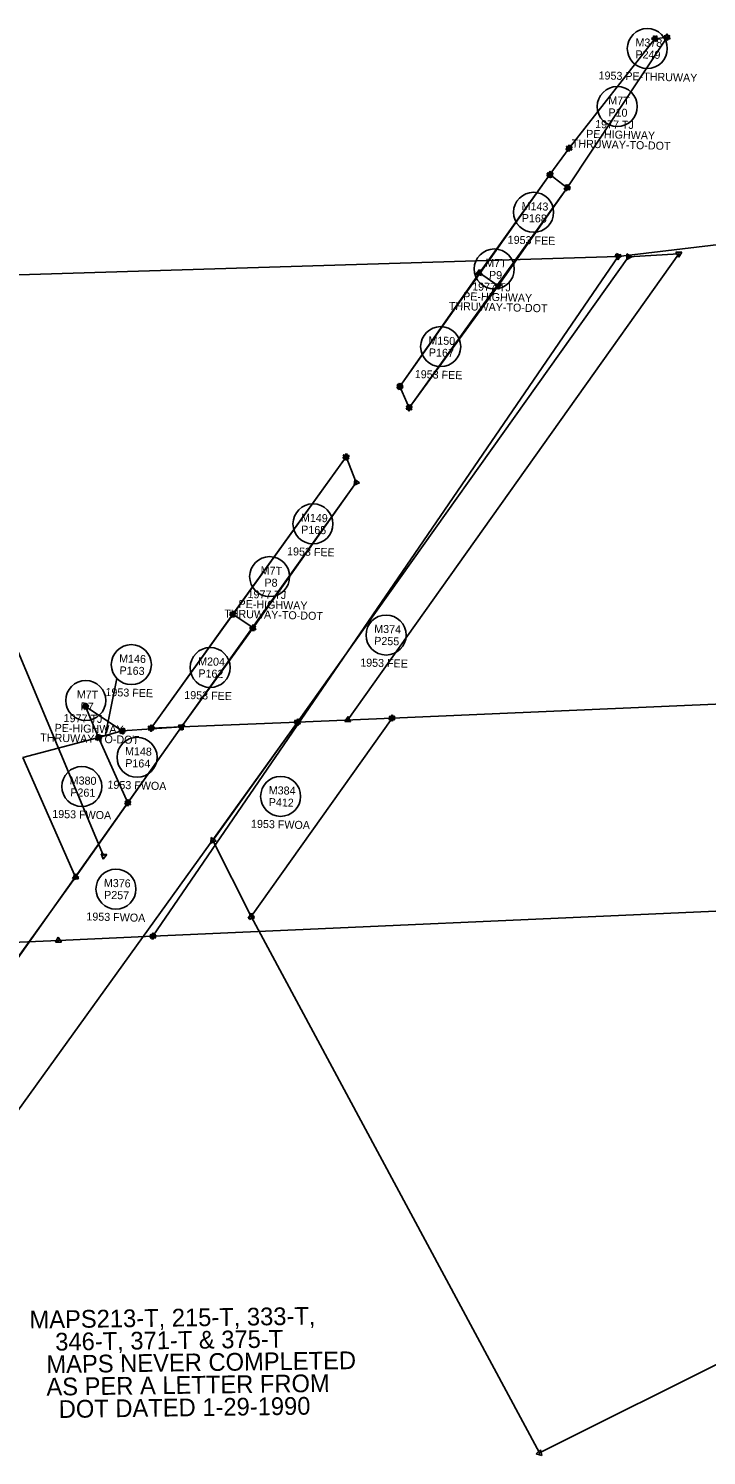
# Model space of a CAD drawing. Extents: x 325018 to 414989, y 1517547 to 1550415.
# Drawn here: x 360104 to 360548, y 1524421 to 1525357 of the extents above; entities that cross this region are included whole.
import ezdxf

# ---------------------------------------------------------------- set-up
doc = ezdxf.new("R2010")
doc.units = 0
for name, color, linetype in [('LAM_I', 7, 'Continuous'), ('Level 56', 7, 'Continuous'), ('MEE', 7, 'Continuous'), ('MHB', 7, 'Continuous'), ('MHBWOA', 7, 'Continuous'), ('MRBL1', 7, 'Continuous'), ('MRBL2', 7, 'Continuous'), ('MRBL3', 7, 'Continuous'), ('S_C', 7, 'Continuous')]:
    doc.layers.add(name, color=color, linetype=linetype)

msp = doc.modelspace()

# ---------------------------------------------------------------- linework, layer by layer
at = {"layer": 'Level 56'}
for centre in [(360509.52, 1525343.75), (360489.82, 1525305.7), (360434.97, 1525236.34), (360409.18, 1525199.15), (360374.05, 1525148.18), (360290.33, 1525031.94), (360261.93, 1524997.34), (360338.27, 1524958.99), (360171.24, 1524939.58), (360222.92, 1524937.68), (360141.36, 1524916.05), (360175, 1524878.79), (360138.8, 1524859.63), (360269.12, 1524853.16), (360161.16, 1524792.34)]:
    msp.add_circle(centre, 13.12, dxfattribs=at)
at = {"layer": 'MEE'}
for p, q in [((360522.5, 1525351.14), (360457, 1525252.39)), ((360514.56, 1525350.2), (360458.21, 1525278.44)), ((360514.56, 1525350.2), (360522.5, 1525351.14)), ((360458.21, 1525278.44), (360445.73, 1525261.05)), ((360347.21, 1525122.03), (360445.73, 1525261.05)), ((360457, 1525252.39), (360353.43, 1525108.09)), ((360353.43, 1525108.09), (360347.21, 1525122.03)), ((360184.24, 1524897.9), (360312, 1525075.85)), ((360312, 1525075.85), (360318.73, 1525059.13)), ((360318.73, 1525059.13), (360204.22, 1524898.78)), ((360141.3, 1524912.11), (360165.33, 1524896.16)), ((360149.8, 1524891.82), (360141.3, 1524912.11))]:
    msp.add_line(p, q, dxfattribs=at)
for points in [[(360512.37, 1525350.23), (360515.67, 1525352.08)], [(360513.44, 1525348.33), (360513.49, 1525352.1)], [(360513.49, 1525352.1), (360516.74, 1525350.17)], [(360515.67, 1525352.08), (360515.62, 1525348.3)], [(360520.58, 1525352.18), (360524.36, 1525352.28)], [(360522.56, 1525348.96), (360520.58, 1525352.18)], [(360520.65, 1525350), (360522.44, 1525353.32)], [(360522.44, 1525353.32), (360524.42, 1525350.1)], [(360524.36, 1525352.28), (360522.56, 1525348.96)], [(360515.62, 1525348.3), (360512.37, 1525350.23)], [(360516.74, 1525350.17), (360513.44, 1525348.33)], [(360524.42, 1525350.1), (360520.65, 1525350)], [(360456.2, 1525277.59), (360458.47, 1525280.61)], [(360459.95, 1525277.13), (360456.2, 1525277.59)], [(360457.95, 1525276.27), (360456.46, 1525279.75)], [(360456.46, 1525279.75), (360460.22, 1525279.29)], [(360460.22, 1525279.29), (360457.95, 1525276.27)], [(360458.47, 1525280.61), (360459.95, 1525277.13)], [(360443.57, 1525261.33), (360447.06, 1525262.78)], [(360446.57, 1525259.03), (360443.57, 1525261.33)], [(360443.74, 1525260.15), (360445.95, 1525263.22)], [(360447.5, 1525259.78), (360443.74, 1525260.15)], [(360445.53, 1525258.88), (360443.96, 1525262.31)], [(360443.96, 1525262.31), (360447.72, 1525261.95)], [(360447.72, 1525261.95), (360445.53, 1525258.88)], [(360445.95, 1525263.22), (360447.5, 1525259.78)], [(360447.06, 1525262.78), (360446.57, 1525259.03)], [(360455.03, 1525251.46), (360457.18, 1525254.57)], [(360458.8, 1525251.15), (360455.03, 1525251.46)], [(360455.32, 1525251), (360456.65, 1525254.54)], [(360459.05, 1525251.62), (360455.32, 1525251)], [(360456.65, 1525254.54), (360459.05, 1525251.62)], [(360457.18, 1525254.57), (360458.8, 1525251.15)], [(360345.23, 1525121.14), (360347.44, 1525124.2)], [(360348.98, 1525120.75), (360345.23, 1525121.14)], [(360347.01, 1525119.86), (360345.44, 1525123.29)], [(360345.44, 1525123.29), (360349.2, 1525122.94)], [(360349.2, 1525122.94), (360347.01, 1525119.86)], [(360347.44, 1525124.2), (360348.98, 1525120.75)], [(360353.21, 1525105.92), (360351.66, 1525109.37)], [(360351.66, 1525109.37), (360355.42, 1525108.99)], [(360355.42, 1525108.99), (360353.21, 1525105.92)], [(360309.99, 1525074.99), (360312.26, 1525078.01)], [(360313.74, 1525074.54), (360309.99, 1525074.99)], [(360312.26, 1525078.01), (360313.74, 1525074.54)], [(360317.42, 1525057.38), (360317.87, 1525061.13)], [(360320.89, 1525058.87), (360317.42, 1525057.38)], [(360317.87, 1525061.13), (360320.89, 1525058.87)], [(360139.12, 1524912.25), (360142.5, 1524913.93)], [(360142.27, 1524910.16), (360139.12, 1524912.25)], [(360139.29, 1524911.27), (360141.57, 1524914.28)], [(360141.57, 1524914.28), (360143.03, 1524910.79)], [(360142.5, 1524913.93), (360142.27, 1524910.16)], [(360143.03, 1524910.79), (360139.29, 1524911.27)], [(360148.85, 1524889.86), (360148.58, 1524893.63)], [(360148.58, 1524893.63), (360151.98, 1524891.98)], [(360163.95, 1524894.47), (360164.54, 1524898.2)], [(360167.48, 1524895.82), (360163.95, 1524894.47)], [(360164.54, 1524898.2), (360167.48, 1524895.82)], [(360182.31, 1524898.91), (360186.08, 1524899.08)], [(360184.34, 1524895.73), (360182.31, 1524898.91)], [(360184.03, 1524895.73), (360182.47, 1524899.17)], [(360182.47, 1524899.17), (360186.23, 1524898.8)], [(360186.23, 1524898.8), (360184.03, 1524895.73)], [(360186.08, 1524899.08), (360184.34, 1524895.73)], [(360202.04, 1524898.84), (360205.36, 1524900.64)], [(360205.26, 1524896.86), (360202.04, 1524898.84)], [(360205.36, 1524900.64), (360205.26, 1524896.86)], [(360151.98, 1524891.98), (360148.85, 1524889.86)]]:
    msp.add_lwpolyline(points, dxfattribs=at)
for centre, radius in [((360514.56, 1525350.2), 0.227), ((360514.56, 1525350.2), 0.227), ((360522.5, 1525351.14), 0.227), ((360522.5, 1525351.14), 0.227), ((360458.21, 1525278.44), 0.227), ((360458.21, 1525278.44), 0.227), ((360445.73, 1525261.05), 1.09), ((360445.73, 1525261.05), 1.09), ((360445.73, 1525261.05), 0.227), ((360457, 1525252.39), 0.227), ((360457, 1525252.39), 0.227), ((360347.22, 1525122.03), 1.09), ((360347.21, 1525122.03), 1.09), ((360353.43, 1525108.09), 0.227), ((360312, 1525075.85), 0.227), ((360318.73, 1525059.13), 0.227), ((360141.3, 1524912.11), 1.09), ((360141.3, 1524912.11), 1.09), ((360165.33, 1524896.16), 0.227), ((360184.24, 1524897.9), 1.09), ((360184.24, 1524897.91), 1.09), ((360204.22, 1524898.78), 0.227), ((360149.8, 1524891.82), 0.227)]:
    msp.add_circle(centre, radius, dxfattribs=at)
at = {"layer": 'MHB'}
for p, q in [((360399.41, 1525196.58), (360445.73, 1525261.05)), ((360445.73, 1525261.05), (360457, 1525252.39)), ((360457, 1525252.39), (360411.79, 1525188.11)), ((360280.21, 1524901.81), (360497.18, 1525207.19)), ((360530.19, 1525209.06), (360313.18, 1524903.29)), ((360497.18, 1525207.19), (360530.19, 1525209.06)), ((360399.41, 1525196.58), (360347.21, 1525122.03)), ((360411.79, 1525188.11), (360399.41, 1525196.58)), ((360353.43, 1525108.09), (360411.79, 1525188.11)), ((360237.83, 1524972.71), (360312, 1525075.85)), ((360318.73, 1525059.13), (360251.03, 1524963.68)), ((360184.24, 1524897.9), (360237.83, 1524972.71)), ((360251.03, 1524963.68), (360237.83, 1524972.71)), ((360251.03, 1524963.68), (360204.22, 1524898.78)), ((360204.22, 1524898.78), (360184.24, 1524897.9))]:
    msp.add_line(p, q, dxfattribs=at)
for points in [[(360443.57, 1525261.33), (360447.06, 1525262.78)], [(360446.57, 1525259.03), (360443.57, 1525261.33)], [(360445.52, 1525258.88), (360443.96, 1525262.32)], [(360443.96, 1525262.32), (360447.72, 1525261.95)], [(360447.72, 1525261.95), (360445.52, 1525258.88)], [(360447.06, 1525262.78), (360446.57, 1525259.03)], [(360455.64, 1525254.09), (360459.16, 1525252.72)], [(360456.21, 1525250.36), (360455.64, 1525254.09)], [(360459.16, 1525252.72), (360456.21, 1525250.36)], [(360496.06, 1525205.31), (360496.13, 1525209.09)], [(360499.36, 1525207.14), (360496.06, 1525205.31)], [(360496.13, 1525209.09), (360499.36, 1525207.14)], [(360528.32, 1525210.19), (360532.09, 1525210.12)], [(360530.14, 1525206.88), (360528.32, 1525210.19)], [(360532.09, 1525210.12), (360530.14, 1525206.88)], [(360397.27, 1525196.2), (360400.16, 1525198.63)], [(360400.81, 1525194.91), (360397.27, 1525196.2)], [(360397.43, 1525195.66), (360399.6, 1525198.76)], [(360401.19, 1525195.33), (360397.43, 1525195.66)], [(360399.6, 1525198.76), (360401.19, 1525195.33)], [(360400.16, 1525198.63), (360400.81, 1525194.91)], [(360409.74, 1525188.85), (360413.46, 1525189.53)], [(360412.18, 1525185.97), (360409.74, 1525188.85)], [(360411.56, 1525185.94), (360410.03, 1525189.4)], [(360410.03, 1525189.4), (360413.79, 1525188.99)], [(360413.79, 1525188.99), (360411.56, 1525185.94)], [(360413.46, 1525189.53), (360412.18, 1525185.97)], [(360345.94, 1525120.25), (360346.31, 1525124.02)], [(360349.38, 1525121.82), (360345.94, 1525120.25)], [(360346.31, 1525124.02), (360349.38, 1525121.82)], [(360351.43, 1525107.2), (360353.66, 1525110.25)], [(360353.66, 1525110.25), (360355.19, 1525106.8)], [(360355.19, 1525106.8), (360351.43, 1525107.2)], [(360311.78, 1525073.68), (360310.23, 1525077.12)], [(360310.23, 1525077.12), (360313.99, 1525076.75)], [(360310.28, 1525077.19), (360314.02, 1525076.66)], [(360311.69, 1525073.69), (360310.28, 1525077.19)], [(360314.02, 1525076.66), (360311.69, 1525073.69)], [(360313.99, 1525076.75), (360311.78, 1525073.68)], [(360317.43, 1525057.38), (360317.87, 1525061.13)], [(360320.9, 1525058.87), (360317.43, 1525057.38)], [(360317.87, 1525061.13), (360320.9, 1525058.87)], [(360235.68, 1524972.34), (360238.58, 1524974.76)], [(360239.23, 1524971.04), (360235.68, 1524972.34)], [(360237.62, 1524970.54), (360236.06, 1524973.98)], [(360236.06, 1524973.98), (360239.82, 1524973.61)], [(360239.82, 1524973.61), (360237.62, 1524970.54)], [(360238.58, 1524974.76), (360239.23, 1524971.04)], [(360248.98, 1524964.43), (360252.7, 1524965.09)], [(360251.42, 1524961.54), (360248.98, 1524964.43)], [(360249.04, 1524962.79), (360251.25, 1524965.85)], [(360252.8, 1524962.41), (360249.04, 1524962.79)], [(360251.25, 1524965.85), (360252.8, 1524962.41)], [(360252.7, 1524965.09), (360251.42, 1524961.54)], [(360140.54, 1524910.06), (360139.91, 1524913.79)], [(360139.91, 1524913.79), (360143.45, 1524912.47)], [(360143.45, 1524912.47), (360140.54, 1524910.06)], [(360280.01, 1524899.63), (360278.44, 1524903.07)], [(360278.44, 1524903.07), (360282.2, 1524902.72)], [(360282.2, 1524902.72), (360280.01, 1524899.63)], [(360311.19, 1524902.38), (360313.38, 1524905.46)], [(360314.95, 1524902.02), (360311.19, 1524902.38)], [(360313.38, 1524905.46), (360314.95, 1524902.02)], [(360148.85, 1524889.86), (360148.58, 1524893.63)], [(360148.58, 1524893.63), (360151.98, 1524891.98)], [(360163.15, 1524896.3), (360166.53, 1524897.98)], [(360166.3, 1524894.21), (360163.15, 1524896.3)], [(360163.22, 1524896.71), (360166.85, 1524897.72)], [(360165.92, 1524894.06), (360163.22, 1524896.71)], [(360166.85, 1524897.72), (360165.92, 1524894.06)], [(360166.53, 1524897.98), (360166.3, 1524894.21)], [(360182.33, 1524896.87), (360184.3, 1524900.09)], [(360186.1, 1524896.76), (360182.33, 1524896.87)], [(360184.3, 1524900.09), (360186.1, 1524896.76)], [(360202.04, 1524898.84), (360205.36, 1524900.64)], [(360205.26, 1524896.86), (360202.04, 1524898.84)], [(360205.36, 1524900.64), (360205.26, 1524896.86)], [(360151.98, 1524891.98), (360148.85, 1524889.86)]]:
    msp.add_lwpolyline(points, dxfattribs=at)
for centre, radius in [((360445.73, 1525261.05), 1.09), ((360445.73, 1525261.05), 1.09), ((360457, 1525252.39), 0.227), ((360497.18, 1525207.19), 0.227), ((360530.19, 1525209.06), 0.227), ((360399.41, 1525196.58), 1.09), ((360399.41, 1525196.58), 0.227), ((360411.79, 1525188.11), 1.09), ((360411.79, 1525188.11), 0.227), ((360347.21, 1525122.03), 0.227), ((360353.43, 1525108.09), 0.227), ((360312, 1525075.85), 1.09), ((360312, 1525075.85), 1.09), ((360318.73, 1525059.13), 0.227), ((360237.83, 1524972.72), 1.09), ((360237.83, 1524972.71), 0.227), ((360251.03, 1524963.68), 1.09), ((360251.03, 1524963.68), 0.227), ((360141.3, 1524912.11), 0.227), ((360280.21, 1524901.81), 1.09), ((360313.18, 1524903.28), 1.09), ((360165.33, 1524896.16), 1.09), ((360165.33, 1524896.16), 1.09), ((360184.24, 1524897.9), 0.227), ((360204.22, 1524898.78), 0.227), ((360149.8, 1524891.82), 0.227)]:
    msp.add_circle(centre, radius, dxfattribs=at)
at = {"layer": 'MHBWOA'}
for p, q in [((360926.64, 1524929.92), (360342.15, 1524904.58)), ((360342.15, 1524904.58), (360249.89, 1524774.32)), ((360342.15, 1524904.58), (360280.21, 1524901.81)), ((360204.22, 1524898.78), (360044.21, 1524673.02)), ((360092.69, 1524641.16), (360280.21, 1524901.81)), ((360165.33, 1524896.16), (360149.8, 1524891.82)), ((360204.22, 1524898.78), (360165.33, 1524896.16)), ((360168.89, 1524848.86), (360204.22, 1524898.78)), ((360280.21, 1524901.81), (360204.22, 1524898.78)), ((360280.21, 1524901.81), (360224.63, 1524824.24)), ((360149.8, 1524891.82), (360100.06, 1524878.72)), ((360149.8, 1524891.82), (360168.89, 1524848.86)), ((360100.06, 1524878.72), (360134.61, 1524800.19)), ((360134.61, 1524800.19), (360168.89, 1524848.86)), ((360224.63, 1524824.24), (360249.89, 1524774.32)), ((360134.61, 1524800.19), (360089.39, 1524737.1)), ((360249.89, 1524774.32), (360438.82, 1524422.43)), ((360438.82, 1524422.43), (361118.26, 1524762.34))]:
    msp.add_line(p, q, dxfattribs=at)
for points in [[(360278.22, 1524900.91), (360280.42, 1524903.98)], [(360278.27, 1524902.82), (360282.05, 1524902.99)], [(360280.31, 1524899.63), (360278.27, 1524902.82)], [(360278.28, 1524902.83), (360282.06, 1524902.98)], [(360280.3, 1524899.63), (360278.28, 1524902.83)], [(360280, 1524899.64), (360278.44, 1524903.08)], [(360278.44, 1524903.08), (360282.2, 1524902.7)], [(360282.2, 1524902.7), (360280, 1524899.64)], [(360282.06, 1524902.98), (360280.3, 1524899.63)], [(360282.05, 1524902.99), (360280.31, 1524899.63)], [(360280.42, 1524903.98), (360281.98, 1524900.54)], [(360340.16, 1524903.67), (360342.35, 1524906.76)], [(360343.93, 1524903.32), (360340.16, 1524903.67)], [(360340.21, 1524905.59), (360343.99, 1524905.76)], [(360342.24, 1524902.41), (360340.21, 1524905.59)], [(360340.24, 1524903.54), (360342.2, 1524906.77)], [(360344.01, 1524903.45), (360340.24, 1524903.54)], [(360342.2, 1524906.77), (360344.01, 1524903.45)], [(360343.99, 1524905.76), (360342.24, 1524902.41)], [(360342.35, 1524906.76), (360343.93, 1524903.32)], [(360147.69, 1524892.4), (360151.35, 1524893.36)], [(360148.01, 1524890.58), (360149.62, 1524894)], [(360149.62, 1524894), (360151.77, 1524890.89)], [(360151.35, 1524893.36), (360150.35, 1524889.72)], [(360163.28, 1524896.92), (360167.01, 1524897.56)], [(360165.7, 1524894.02), (360163.28, 1524896.92)], [(360167.01, 1524897.56), (360165.7, 1524894.02)], [(360202.04, 1524898.84), (360205.36, 1524900.64)], [(360205.26, 1524896.86), (360202.04, 1524898.84)], [(360202.26, 1524899.74), (360206.03, 1524900)], [(360204.37, 1524896.6), (360202.26, 1524899.74)], [(360204.02, 1524896.6), (360202.44, 1524900.04)], [(360202.44, 1524900.04), (360206.21, 1524899.69)], [(360206.21, 1524899.69), (360204.02, 1524896.6)], [(360206.03, 1524900), (360204.37, 1524896.6)], [(360205.36, 1524900.64), (360205.26, 1524896.86)], [(360281.98, 1524900.54), (360278.22, 1524900.91)], [(360150.35, 1524889.72), (360147.69, 1524892.4)], [(360151.77, 1524890.89), (360148.01, 1524890.58)], [(360166.9, 1524847.96), (360169.1, 1524851.03)], [(360170.66, 1524847.59), (360166.9, 1524847.96)], [(360168.7, 1524846.69), (360167.11, 1524850.12)], [(360167.11, 1524850.12), (360170.87, 1524849.78)], [(360170.87, 1524849.78), (360168.7, 1524846.69)], [(360169.1, 1524851.03), (360170.66, 1524847.59)], [(360223.39, 1524822.44), (360223.68, 1524826.21)], [(360226.8, 1524824.08), (360223.39, 1524822.44)], [(360223.68, 1524826.21), (360226.8, 1524824.08)], [(360132.62, 1524799.29), (360134.83, 1524802.36)], [(360133.33, 1524798.43), (360133.72, 1524802.18)], [(360136.78, 1524799.97), (360133.33, 1524798.43)], [(360133.72, 1524802.18), (360136.78, 1524799.97)], [(360134.83, 1524802.36), (360136.38, 1524798.91)], [(360136.38, 1524798.91), (360132.62, 1524799.29)], [(360247.92, 1524773.37), (360250.05, 1524776.5)], [(360251.69, 1524773.09), (360247.92, 1524773.37)], [(360248.68, 1524772.51), (360248.91, 1524776.28)], [(360252.06, 1524774.19), (360248.68, 1524772.51)], [(360248.91, 1524776.28), (360252.06, 1524774.19)], [(360250.05, 1524776.5), (360251.69, 1524773.09)], [(360436.69, 1524421.95), (360439.48, 1524424.5)], [(360440.29, 1524420.81), (360436.69, 1524421.95)], [(360439.48, 1524424.5), (360440.29, 1524420.81)]]:
    msp.add_lwpolyline(points, dxfattribs=at)
for centre, radius in [((360280.21, 1524901.81), 1.09), ((360280.21, 1524901.81), 1.09), ((360280.21, 1524901.81), 1.09), ((360280.21, 1524901.81), 1.09), ((360342.15, 1524904.58), 1.09), ((360342.15, 1524904.58), 1.09), ((360342.15, 1524904.58), 0.227), ((360165.33, 1524896.16), 0.227), ((360204.22, 1524898.78), 1.09), ((360204.22, 1524898.78), 1.09), ((360204.22, 1524898.78), 0.227), ((360149.8, 1524891.82), 1.09), ((360149.8, 1524891.82), 0.227), ((360168.89, 1524848.86), 1.09), ((360168.89, 1524848.86), 0.227), ((360224.63, 1524824.24), 0.227), ((360134.61, 1524800.19), 0.227), ((360134.61, 1524800.19), 0.227), ((360249.89, 1524774.32), 0.227), ((360249.89, 1524774.32), 0.227), ((360438.82, 1524422.43), 0.227)]:
    msp.add_circle(centre, radius, dxfattribs=at)
at = {"layer": 'MRBL1'}
for p, q in [((360490.4, 1525207.39), (360750.98, 1525238.11)), ((360185.4, 1524761.43), (360490.4, 1525207.39))]:
    msp.add_line(p, q, dxfattribs=at)
for points in [[(360489.35, 1525205.48), (360489.27, 1525209.26)], [(360489.27, 1525209.26), (360492.58, 1525207.44)], [(360492.58, 1525207.44), (360489.35, 1525205.48)], [(360185.23, 1524759.25), (360183.6, 1524762.65)], [(360183.6, 1524762.65), (360187.37, 1524762.37)], [(360187.37, 1524762.37), (360185.23, 1524759.25)]]:
    msp.add_lwpolyline(points, dxfattribs=at)
for centre, radius in [((360490.4, 1525207.39), 0.227), ((360185.4, 1524761.43), 1.09)]:
    msp.add_circle(centre, radius, dxfattribs=at)
at = {"layer": 'MRBL2'}
for p, q in [((360490.4, 1525207.39), (359994.63, 1525192.19)), ((360185.4, 1524761.43), (360836.78, 1524790.6)), ((357680.4, 1524649.21), (360123.46, 1524758.65)), ((360123.46, 1524758.65), (360185.4, 1524761.43))]:
    msp.add_line(p, q, dxfattribs=at)
for points in [[(360488.48, 1525208.43), (360492.25, 1525208.54)], [(360490.47, 1525205.22), (360488.48, 1525208.43)], [(360492.25, 1525208.54), (360490.47, 1525205.22)], [(360183.56, 1524760.25), (360185.3, 1524763.6)], [(360185.3, 1524763.6), (360187.33, 1524760.42)], [(360121.62, 1524757.47), (360123.36, 1524760.83)], [(360125.4, 1524757.64), (360121.62, 1524757.47)], [(360123.36, 1524760.83), (360125.4, 1524757.64)], [(360187.33, 1524760.42), (360183.56, 1524760.25)]]:
    msp.add_lwpolyline(points, dxfattribs=at)
for centre, radius in [((360490.4, 1525207.39), 1.09), ((360123.46, 1524758.65), 0.227), ((360185.4, 1524761.43), 0.227)]:
    msp.add_circle(centre, radius, dxfattribs=at)
at = {"layer": 'MRBL3'}
msp.add_line((359994.63, 1525192.19), (360153.1, 1524814.1), dxfattribs=at)
for points in [[(360151.36, 1524815.42), (360155.11, 1524814.94)], [(360152.82, 1524811.93), (360151.36, 1524815.42)], [(360155.11, 1524814.94), (360152.82, 1524811.93)]]:
    msp.add_lwpolyline(points, dxfattribs=at)
msp.add_circle((360153.1, 1524814.09), 1.09, dxfattribs=at)
at = {"layer": 'S_C'}
msp.add_line((360154.23, 1524893.69), (360161.73, 1524930.54), dxfattribs=at)

# ---------------------------------------------------------------- texts
at = {"layer": 'LAM_I'}
for s, p in [('MAPS213-T, 215-T, 333-T,', (360104.53, 1524504.11)), ('346-T, 371-T & 375-T', (360121.42, 1524489.59)), ('MAPS NEVER COMPLETED', (360115.63, 1524474.78)), ('AS PER A LETTER FROM', (360115.65, 1524460.04)), ('DOT DATED 1-29-1990', (360123.71, 1524445.4))]:
    msp.add_text(s, height=11.6264, rotation=0.76966, dxfattribs=at).set_placement(p)
at = {"layer": 'Level 56'}
for s, height, p in [('P249', 5.249, (360501.67, 1525337.39)), ('M378', 5.249, (360501.68, 1525345.26)), ('1953 PE-THRUWAY', 5.2493, (360477.53, 1525323.56)), ('M7T', 5.249, (360483.88, 1525307.17)), ('1977 TJ', 5.249, (360475.28, 1525291.63)), ('P10', 5.249, (360483.97, 1525299.29)), ('PE-HIGHWAY', 5.249, (360469.36, 1525285.21)), ('THRUWAY-TO-DOT', 5.2493, (360459.97, 1525278.88)), ('M143', 5.249, (360427.06, 1525237.86)), ('P168', 5.249, (360427.18, 1525229.98)), ('1953 FEE', 5.249, (360417.95, 1525215.76)), ('M7T', 5.249, (360403.23, 1525200.62)), ('P9', 5.249, (360405.68, 1525192.68)), ('PE-HIGHWAY', 5.249, (360388.72, 1525178.66)), ('1977 TJ', 5.249, (360394.64, 1525185.08)), ('THRUWAY-TO-DOT', 5.2493, (360379.33, 1525172.33)), ('M150', 5.249, (360365.95, 1525149.7)), ('P167', 5.249, (360366.26, 1525141.81)), ('1953 FEE', 5.249, (360357.03, 1525127.6)), ('M149', 5.249, (360282.39, 1525033.46)), ('P165', 5.249, (360282.55, 1525025.58)), ('1953 FEE', 5.249, (360273.31, 1525011.36)), ('M7T', 5.249, (360255.98, 1524998.8)), ('P8', 5.249, (360258.45, 1524990.86)), ('1977 TJ', 5.249, (360247.39, 1524983.27)), ('PE-HIGHWAY', 5.249, (360241.47, 1524976.85)), ('THRUWAY-TO-DOT', 5.2493, (360232.08, 1524970.52)), ('M374', 5.249, (360330.43, 1524960.51)), ('P255', 5.249, (360330.45, 1524952.63)), ('M146', 5.249, (360163.19, 1524941.1)), ('M204', 5.249, (360214.99, 1524939.2)), ('1953 FEE', 5.249, (360321.25, 1524938.42)), ('P163', 5.249, (360163.47, 1524933.22)), ('P162', 5.249, (360215.13, 1524931.32)), ('M7T', 5.249, (360135.42, 1524917.52)), ('1953 FEE', 5.249, (360154.22, 1524919)), ('1953 FEE', 5.249, (360205.89, 1524917.1)), ('P7', 5.249, (360137.88, 1524909.57)), ('1977 TJ', 5.249, (360126.83, 1524901.98)), ('THRUWAY-TO-DOT', 5.2493, (360111.51, 1524889.23)), ('PE-HIGHWAY', 5.249, (360120.9, 1524895.56)), ('M148', 5.249, (360167.07, 1524880.31)), ('P164', 5.249, (360167.21, 1524872.42)), ('M380', 5.249, (360130.76, 1524861.15)), ('P261', 5.249, (360131.18, 1524853.26)), ('1953 FWOA', 5.249, (360155.55, 1524858.27)), ('M384', 5.249, (360261.28, 1524854.68)), ('P412', 5.249, (360261.28, 1524846.8)), ('1953 FWOA', 5.249, (360119.35, 1524839.11)), ('1953 FWOA', 5.249, (360249.67, 1524832.65)), ('M376', 5.249, (360153.19, 1524793.86)), ('P257', 5.249, (360153.34, 1524785.98)), ('1953 FWOA', 5.249, (360141.71, 1524771.83))]:
    msp.add_text(s, height=height, rotation=358.51411, dxfattribs=at).set_placement(p)

doc.saveas('drawing.dxf')
